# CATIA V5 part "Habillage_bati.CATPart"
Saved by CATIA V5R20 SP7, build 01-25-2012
Part number: Habillage_bati
Bounding box of the stored display mesh (mm): x -9.1 to 2.6, y -67.527 to 52.473, z -43.873 to 64.499
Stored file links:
  F:\IAO\Catia\Habillage_bati.CATPart
  F:\IAO\Catia\asandre.CATProduct
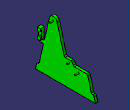
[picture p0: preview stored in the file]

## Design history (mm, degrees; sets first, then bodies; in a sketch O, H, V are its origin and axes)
Set1
  Plane1 "plan.bati": linked copy from another document
  Point1 "C": linked copy from another document
  Point2 "K": linked copy from another document
  Point3 "F": linked copy from another document
  Point4 "machoires.a'": linked copy from another document
Body1 (main body)
  Sketch1 "Bati" on Plane1, origin (-4.1, 0, 0), H (0, 1, 0), V (0, 0, 1)
    point P1 (-50, 13.4187)
    line L1 (-49.5576, 15.3644) -> (-39.8009, 58.2738)
    point P2 (-39.8009, 58.2738)
    arc A1 centre (-32, 56.5) radius 8 from (-39.8009, 58.2738) to (-24.2726, 58.5706) cw
    point P3 (-32, 56.5)
    point P4 (-24.2726, 58.5706)
    line L2 (-24.2726, 58.5706) -> (-10.534, 7.2976)
    point P5 (-10.0375, 5.4446)
    line L3 (-8.1192, 5.4446) -> (3.4784, 5.4446)
    point P6 (4.9625, 5.4446)
    line L4 (5.6731, 4.1418) -> (8.0827, -0.2756)
    point P7 (8.7934, -1.5785)
    line L5 (10.2775, -1.5785) -> (34.7219, -1.5785)
    point P8 (49.1806, -31.5857)
    line L6 (49.6771, -33.4387) -> (52.473, -43.8732)
    line L7 (52.473, -43.8732) -> (-67.527, -43.8732)
    point P11 (-60.2331, -31.5857)
    line L8 (-59.7907, -29.64) -> (-51.6421, 6.197)
    point P12 (-51.3643, 7.4187)
    line L9 (-52.6172, 7.4187) -> (-58.5, 7.4187)
    line L10 (-61, 9.9187) -> (-61, 32.9187)
    line L11 (-61, 32.9187) -> (-55, 32.9187)
    line L12 (-55, 32.9187) -> (-55, 15.4187)
    point P15 (-55, 13.4187)
    line L13 (-52.5, 13.4187) -> (-51.9954, 13.4187)
    point P16 (-50, 13.4187)
    reference projected point E1 (-32, 56.5) from Point1
    axis line L14 (-32, 56.5) -> (-32, -20.5)
    line L15 (-62.2284, -31.5857) -> (-62.7377, -31.5857)
    point P18 (-64.7331, -31.5857)
    line L16 (-65.1755, -33.5314) -> (-67.527, -43.8732)
    line L17 (37.1367, -3.4314) -> (44.1841, -29.7328)
    point P19 (44.6806, -31.5857)
    line L18 (46.5989, -31.5857) -> (47.2623, -31.5857)
    arc A2 centre (-51.9954, 15.9187) radius 2.5 from (-49.5576, 15.3644) to (-51.9954, 13.4187) cw
    arc A3 centre (-58.5, 9.9187) radius 2.5 from (-61, 9.9187) to (-58.5, 7.4187) ccw
    arc A4 centre (-52.6172, 6.4187) radius 1 from (-52.6172, 7.4187) to (-51.6421, 6.197) cw
    arc A5 centre (-62.2284, -29.0857) radius 2.5 from (-59.7907, -29.64) to (-62.2284, -31.5857) cw
    arc A6 centre (-62.7377, -34.0857) radius 2.5 from (-62.7377, -31.5857) to (-65.1755, -33.5314) ccw
    point P34 (-62.7377, -31.5857)
    arc A7 centre (47.2623, -34.0857) radius 2.5 from (47.2623, -31.5857) to (49.6771, -33.4387) cw
    point P37 (47.2623, -31.5857)
    arc A8 centre (46.5989, -29.0857) radius 2.5 from (44.1841, -29.7328) to (46.5989, -31.5857) ccw
    arc A9 centre (34.7219, -4.0785) radius 2.5 from (34.7219, -1.5785) to (37.1367, -3.4314) cw
    arc A10 centre (10.2775, 0.9215) radius 2.5 from (10.2775, -1.5785) to (8.0827, -0.2756) cw
    arc A11 centre (3.4784, 2.9446) radius 2.5 from (5.6731, 4.1418) to (3.4784, 5.4446) ccw
    arc A12 centre (-8.1192, 7.9446) radius 2.5 from (-8.1192, 5.4446) to (-10.534, 7.2976) cw
    reference projected point E2 (-58, 22.5) from Point4
    line L19 (-55, 15.4187) -> (-55, 13.4187)
    line L20 (-52.5, 13.4187) -> (-55, 13.4187)
    radius A1 = 8
    angle L2 L14 = 15
    distance L10 L12 = 6
    distance L13 L9 = 6
    length L7 = 120
    distance P1 P2 = 46
    distance P15 P16 = 5
    radius A2 = 2.5
    radius A3 = 2.5
    distance P11 P12 = 40
    radius A4 = 1
    distance P11 P18 = 4.5
    radius A5 = 2.5
    radius A6 = 2.5
    distance P19 P8 = 4.5
    radius A7 = 2.5
    radius A8 = 2.5
    radius A9 = 2.5
    distance P37 P34 = 110
    distance P6 P7 = 8
    radius A10 = 2.5
    distance P5 P6 = 15
    radius A11 = 2.5
    distance P4 P5 = 55
    radius A12 = 2.5
    length L10 = 23
    distance L12 E2 = 3
    tangency: A1 L1, L4 A1, L2 A1, A2 L1, A2 L13, A3 L10, A3 L9, A4 L9, A4 L8, A5 L8, A5 L15, A6 L15, A6 L16, A7 L18, A7 L6, A8 L17, A8 L18, A9 L5, A9 L17, A10 L5, A10 L4, A11 L4, A11 L3, A12 L3, A12 L2, L20 A2
    vertical: L10 V, L14 V, L12 V, L19 V
    horizontal: L11 H, L13 H, L3 H, L7 H, L15 H, L5 H, L18 H
    coincidence: P16 L1, P3 E1, P1 P16, P12 L1, L18 L15, L1 P1, L13 P16, L13 P15, L12 P15, L9 P12, L8 P12, L8 P11, L15 P11, L15 P18, L16 P18, L18 P8, L6 P8, L17 P19, L18 P19, L5 P7, L4 P7, L4 P6, L3 P6, L3 P5, L2 P5
    parallelism: L1 L8, L17 L2, L16 L8, L6 L17
  Pad1 "Bati": profile Sketch1, direction (-1, 0, 0), length 5
  Sketch2 "Pivot.C" on Plane1, origin (-4.1, 0, 0), H (0, 1, 0), V (0, 0, 1)
    circle A1 centre (-32, 56.5) radius 1.5
    point P1 (-32, 56.5)
    reference projected point E1 (-32, 56.5) from Point1
    radius A1 = 1.5
    coincidence: P1 E1
  Pad2 "Pivot.C": profile Sketch2, direction (1, 0, 0), length 6.5
  Sketch3 "Pivot.K" on Plane1, origin (-4.1, 0, 0), H (0, 1, 0), V (0, 0, 1)
    circle A1 centre (0, 0) radius 1.5
    point P1 (0, 0)
    reference projected point E1 (0, 0) from Point2
    radius A1 = 1.5
    coincidence: P1 E1
  Pad3 "Pivot.K": profile Sketch3, direction (1, 0, 0), length 4
  Sketch4 "Pivot.F" on Plane1, origin (-4.1, 0, 0), H (0, 1, 0), V (0, 0, 1)
    circle A1 centre (18.5, -8.5) radius 1.5
    point P1 (18.5, -8.5)
    point P2 (37, 0)
    reference projected point E1 (18.5, -8.5) from Point3
    radius A1 = 1.5
    coincidence: P1 E1
  Pad4 "Pivot.F": profile Sketch4, direction (1, 0, 0), length 6.7
  Sketch5 "Machoires.a" on Plane1, origin (-4.1, 0, 0), H (0, 1, 0), V (0, 0, 1)
    point P1 (-61, 32.9187)
    line L1 (-61, 32.9187) -> (-61, 29.0187)
    point P2 (-61, 29.0187)
    arc A1 centre (-58, 29.0187) radius 3 from (-61, 29.0187) to (-55, 29.0187) ccw
    point P4 (-55, 29.0187)
    line L2 (-55, 29.0187) -> (-55, 32.9187)
    point P5 (-55, 32.9187)
    line L3 (-55, 32.9187) -> (-61, 32.9187)
    reference projected line E1 (-55, 32.9187) -> (-61, 32.9187) from edge [face of Pad1 from Sketch1.L11 | start face of Pad1]
    reference projected line E2 (-55, 15.4187) -> (-55, 32.9187) from edge [face of Pad1 from Sketch1.L12 | start face of Pad1]
    reference projected line E3 (-61, 32.9187) -> (-61, 9.9187) from edge [face of Pad1 from Sketch1.L10 | start face of Pad1]
    axis line L4 (-70, 22.5) -> (-58, 22.5)
    point P7 (-58, 22.5)
    reference projected point E4 (-58, 22.5) from Point4
    point P8 (-55, 15.9813)
    point P9 (-61, 15.9813)
    arc A2 centre (-58, 15.9813) radius 3 from (-61, 15.9813) to (-55, 15.9813) cw
    point P11 (-61, 12.0813)
    line L5 (-61, 12.0813) -> (-61, 15.9813)
    point P12 (-55, 12.0813)
    line L6 (-55, 12.0813) -> (-61, 12.0813)
    line L7 (-55, 15.9813) -> (-55, 12.0813)
    length L1 = 3.9
    vertical: L1 V
    tangency: A1 L1, L2 A1
    horizontal: L3 H, L4 H
    coincidence: L3 E1, L2 E2, L1 E3, P7 E4
    symmetry: P4 P8 L4, P2 P9 L4, A1 A2 L4, P1 P11 L4, L1 L5 L4, P5 P12 L4, L3 L6 L4, L2 L7 L4
  Pad5 "Machoires.a": profile Sketch5, direction (1, 0, 0), length 2.6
